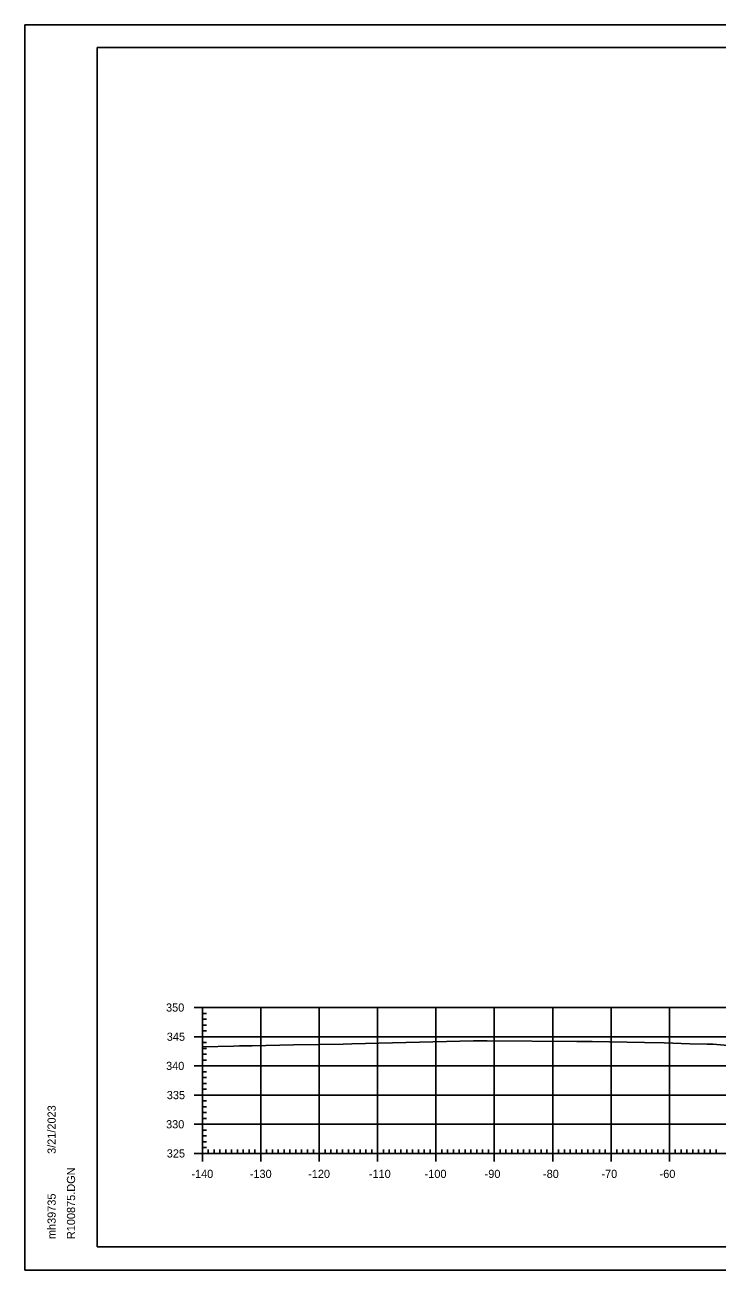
# Model space of a CAD drawing. Extents: x 1368122 to 1710785, y 373130 to 557566.
# Drawn here: x 1368122.3 to 1368240.8, y 374439.7 to 374653.1 of the extents above; entities that cross this region are included whole.
import ezdxf

# ---------------------------------------------------------------- set-up
doc = ezdxf.new("R2010")
doc.units = 0
for name, color, linetype in [('R_Axis', 7, 'Continuous'), ('R_Axis Annot', 7, 'Continuous'), ('R_Border', 7, 'Continuous'), ('R_Exist Surface', 7, 'Continuous'), ('R_Grid', 7, 'Continuous'), ('R_No Plot', 7, 'Continuous')]:
    doc.layers.add(name, color=color, linetype=linetype)

msp = doc.modelspace()

# ---------------------------------------------------------------- linework, layer by layer
at = {"layer": 'R_Axis'}
for p, q in [((1368151.29, 374484.71), (1368154.09, 374484.71)), ((1368152.69, 374459.71), (1368152.69, 374484.71)), ((1368152.69, 374483.71), (1368153.39, 374483.71)), ((1368152.69, 374482.71), (1368153.39, 374482.71)), ((1368152.69, 374481.71), (1368153.39, 374481.71)), ((1368152.69, 374480.71), (1368153.39, 374480.71)), ((1368151.29, 374479.71), (1368154.09, 374479.71)), ((1368152.69, 374478.71), (1368153.39, 374478.71)), ((1368152.69, 374477.71), (1368153.39, 374477.71)), ((1368152.69, 374476.71), (1368153.39, 374476.71)), ((1368151.29, 374474.71), (1368154.09, 374474.71)), ((1368152.69, 374475.71), (1368153.39, 374475.71)), ((1368152.69, 374473.71), (1368153.39, 374473.71)), ((1368152.69, 374472.71), (1368153.39, 374472.71)), ((1368152.69, 374471.71), (1368153.39, 374471.71)), ((1368151.29, 374469.71), (1368154.09, 374469.71)), ((1368152.69, 374470.71), (1368153.39, 374470.71)), ((1368152.69, 374468.71), (1368153.39, 374468.71)), ((1368152.69, 374467.71), (1368153.39, 374467.71)), ((1368152.69, 374466.71), (1368153.39, 374466.71)), ((1368152.69, 374465.71), (1368153.39, 374465.71)), ((1368151.29, 374464.71), (1368154.09, 374464.71)), ((1368152.69, 374463.71), (1368153.39, 374463.71)), ((1368152.69, 374462.71), (1368153.39, 374462.71)), ((1368152.69, 374461.71), (1368153.39, 374461.71)), ((1368152.69, 374458.31), (1368152.69, 374461.11)), ((1368162.69, 374458.31), (1368162.69, 374461.11)), ((1368172.69, 374458.31), (1368172.69, 374461.11)), ((1368182.69, 374458.31), (1368182.69, 374461.11)), ((1368192.69, 374458.31), (1368192.69, 374461.11)), ((1368202.69, 374458.31), (1368202.69, 374461.11)), ((1368212.69, 374458.31), (1368212.69, 374461.11)), ((1368222.69, 374458.31), (1368222.69, 374461.11)), ((1368232.69, 374458.31), (1368232.69, 374461.11)), ((1368151.29, 374459.71), (1368154.09, 374459.71)), ((1368152.69, 374460.71), (1368153.39, 374460.71)), ((1368152.69, 374459.71), (1368432.69, 374459.71)), ((1368153.69, 374459.71), (1368153.69, 374460.41)), ((1368154.69, 374459.71), (1368154.69, 374460.41)), ((1368155.69, 374459.71), (1368155.69, 374460.41)), ((1368156.69, 374459.71), (1368156.69, 374460.41)), ((1368157.69, 374459.71), (1368157.69, 374460.41)), ((1368158.69, 374459.71), (1368158.69, 374460.41)), ((1368159.69, 374459.71), (1368159.69, 374460.41)), ((1368160.69, 374459.71), (1368160.69, 374460.41)), ((1368161.69, 374459.71), (1368161.69, 374460.41)), ((1368163.69, 374459.71), (1368163.69, 374460.41)), ((1368164.69, 374459.71), (1368164.69, 374460.41)), ((1368165.69, 374459.71), (1368165.69, 374460.41)), ((1368166.69, 374459.71), (1368166.69, 374460.41)), ((1368167.69, 374459.71), (1368167.69, 374460.41)), ((1368168.69, 374459.71), (1368168.69, 374460.41)), ((1368169.69, 374459.71), (1368169.69, 374460.41)), ((1368170.69, 374459.71), (1368170.69, 374460.41)), ((1368171.69, 374459.71), (1368171.69, 374460.41)), ((1368173.69, 374459.71), (1368173.69, 374460.41)), ((1368174.69, 374459.71), (1368174.69, 374460.41)), ((1368175.69, 374459.71), (1368175.69, 374460.41)), ((1368176.69, 374459.71), (1368176.69, 374460.41)), ((1368177.69, 374459.71), (1368177.69, 374460.41)), ((1368178.69, 374459.71), (1368178.69, 374460.41)), ((1368179.69, 374459.71), (1368179.69, 374460.41)), ((1368180.69, 374459.71), (1368180.69, 374460.41)), ((1368181.69, 374459.71), (1368181.69, 374460.41)), ((1368183.69, 374459.71), (1368183.69, 374460.41)), ((1368184.69, 374459.71), (1368184.69, 374460.41)), ((1368185.69, 374459.71), (1368185.69, 374460.41)), ((1368186.69, 374459.71), (1368186.69, 374460.41)), ((1368187.69, 374459.71), (1368187.69, 374460.41)), ((1368188.69, 374459.71), (1368188.69, 374460.41)), ((1368189.69, 374459.71), (1368189.69, 374460.41)), ((1368190.69, 374459.71), (1368190.69, 374460.41)), ((1368191.69, 374459.71), (1368191.69, 374460.41)), ((1368193.69, 374459.71), (1368193.69, 374460.41)), ((1368194.69, 374459.71), (1368194.69, 374460.41)), ((1368195.69, 374459.71), (1368195.69, 374460.41)), ((1368196.69, 374459.71), (1368196.69, 374460.41)), ((1368197.69, 374459.71), (1368197.69, 374460.41)), ((1368198.69, 374459.71), (1368198.69, 374460.41)), ((1368199.69, 374459.71), (1368199.69, 374460.41)), ((1368200.69, 374459.71), (1368200.69, 374460.41)), ((1368201.69, 374459.71), (1368201.69, 374460.41)), ((1368203.69, 374459.71), (1368203.69, 374460.41)), ((1368204.69, 374459.71), (1368204.69, 374460.41)), ((1368205.69, 374459.71), (1368205.69, 374460.41)), ((1368206.69, 374459.71), (1368206.69, 374460.41)), ((1368207.69, 374459.71), (1368207.69, 374460.41)), ((1368208.69, 374459.71), (1368208.69, 374460.41)), ((1368209.69, 374459.71), (1368209.69, 374460.41)), ((1368210.69, 374459.71), (1368210.69, 374460.41)), ((1368211.69, 374459.71), (1368211.69, 374460.41)), ((1368213.69, 374459.71), (1368213.69, 374460.41)), ((1368214.69, 374459.71), (1368214.69, 374460.41)), ((1368215.69, 374459.71), (1368215.69, 374460.41)), ((1368216.69, 374459.71), (1368216.69, 374460.41)), ((1368217.69, 374459.71), (1368217.69, 374460.41)), ((1368218.69, 374459.71), (1368218.69, 374460.41)), ((1368219.69, 374459.71), (1368219.69, 374460.41)), ((1368220.69, 374459.71), (1368220.69, 374460.41)), ((1368221.69, 374459.71), (1368221.69, 374460.41)), ((1368223.69, 374459.71), (1368223.69, 374460.41)), ((1368224.69, 374459.71), (1368224.69, 374460.41)), ((1368225.69, 374459.71), (1368225.69, 374460.41)), ((1368226.69, 374459.71), (1368226.69, 374460.41)), ((1368227.69, 374459.71), (1368227.69, 374460.41)), ((1368228.69, 374459.71), (1368228.69, 374460.41)), ((1368229.69, 374459.71), (1368229.69, 374460.41)), ((1368230.69, 374459.71), (1368230.69, 374460.41)), ((1368231.69, 374459.71), (1368231.69, 374460.41)), ((1368233.69, 374459.71), (1368233.69, 374460.41)), ((1368234.69, 374459.71), (1368234.69, 374460.41)), ((1368235.69, 374459.71), (1368235.69, 374460.41)), ((1368236.69, 374459.71), (1368236.69, 374460.41)), ((1368237.69, 374459.71), (1368237.69, 374460.41)), ((1368238.69, 374459.71), (1368238.69, 374460.41)), ((1368239.69, 374459.71), (1368239.69, 374460.41)), ((1368240.69, 374459.71), (1368240.69, 374460.41))]:
    msp.add_line(p, q, dxfattribs=at)
at = {"layer": 'R_Border'}
for p, q in [((1368134.69, 374649.17), (1368450.87, 374649.17)), ((1368134.69, 374443.71), (1368134.69, 374649.17)), ((1368134.69, 374443.71), (1368134.69, 374443.71)), ((1368450.87, 374443.71), (1368134.69, 374443.71))]:
    msp.add_line(p, q, dxfattribs=at)
at = {"layer": 'R_Exist Surface'}
msp.add_lwpolyline([(1368152.69, 374477.96), (1368158, 374478.1), (1368159.06, 374478.12), (1368161.19, 374478.14), (1368168.3, 374478.29), (1368176.81, 374478.45), (1368178.27, 374478.48), (1368199.12, 374478.98), (1368199.87, 374478.99), (1368201.47, 374478.98), (1368216.81, 374478.89), (1368219.45, 374478.86), (1368228.44, 374478.72), (1368231.78, 374478.64), (1368236.18, 374478.48), (1368239.17, 374478.45), (1368240.18, 374478.42), (1368242.69, 374478.21)], dxfattribs=at)
at = {"layer": 'R_Grid'}
for p, q in [((1368152.69, 374484.71), (1368432.69, 374484.71)), ((1368152.69, 374459.71), (1368152.69, 374484.71)), ((1368162.69, 374459.71), (1368162.69, 374484.71)), ((1368172.69, 374459.71), (1368172.69, 374484.71)), ((1368182.69, 374459.71), (1368182.69, 374484.71)), ((1368192.69, 374459.71), (1368192.69, 374484.71)), ((1368202.69, 374459.71), (1368202.69, 374484.71)), ((1368212.69, 374459.71), (1368212.69, 374484.71)), ((1368222.69, 374459.71), (1368222.69, 374484.71)), ((1368232.69, 374459.71), (1368232.69, 374484.71)), ((1368152.69, 374479.71), (1368432.69, 374479.71)), ((1368152.69, 374474.71), (1368432.69, 374474.71)), ((1368152.69, 374469.71), (1368432.69, 374469.71)), ((1368152.69, 374464.71), (1368432.69, 374464.71)), ((1368152.69, 374459.71), (1368432.69, 374459.71))]:
    msp.add_line(p, q, dxfattribs=at)
at = {"layer": 'R_No Plot'}
for p, q in [((1368122.29, 374653.06), (1368455.63, 374653.06)), ((1368122.29, 374439.73), (1368455.63, 374439.73))]:
    msp.add_line(p, q, dxfattribs=at)
for points in [[(1368122.29, 374653.06), (1368455.63, 374653.06), (1368455.63, 374439.72), (1368122.29, 374439.72)], [(1368368.61, 374649.17), (1368388.23, 374649.17), (1368388.23, 374639.29), (1368404.34, 374639.29), (1368427.54, 374639.29), (1368427.66, 374611.13), (1368450.87, 374611.13), (1368450.87, 374443.71), (1368134.69, 374443.71), (1368134.69, 374649.17)]]:
    msp.add_lwpolyline(points, close=True, dxfattribs=at)

# ---------------------------------------------------------------- texts
at = {"layer": 'R_Axis Annot'}
for s, p in [('350', (1368146.46, 374484.01)), ('345', (1368146.59, 374479.01)), ('340', (1368146.46, 374474.01)), ('335', (1368146.59, 374469.01)), ('330', (1368146.46, 374464.01)), ('325', (1368146.59, 374459.01)), ('-140', (1368150.8, 374455.51)), ('-130', (1368160.8, 374455.51)), ('-120', (1368170.8, 374455.51)), ('-110', (1368181.2, 374455.51)), ('-100', (1368190.75, 374455.51)), ('-90', (1368201.03, 374455.51)), ('-80', (1368211.03, 374455.51)), ('-70', (1368221.03, 374455.51)), ('-60', (1368231, 374455.51))]:
    msp.add_text(s, height=1.4, dxfattribs=at).set_placement(p)
at = {"layer": 'R_Border'}
for s, p in [('3/21/2023', (1368127.56, 374459.63)), ('R100875.DGN', (1368130.88, 374445.03)), ('mh39735', (1368127.56, 374445.03))]:
    msp.add_text(s, height=1.4, rotation=90, dxfattribs=at).set_placement(p)

doc.saveas('drawing.dxf')
